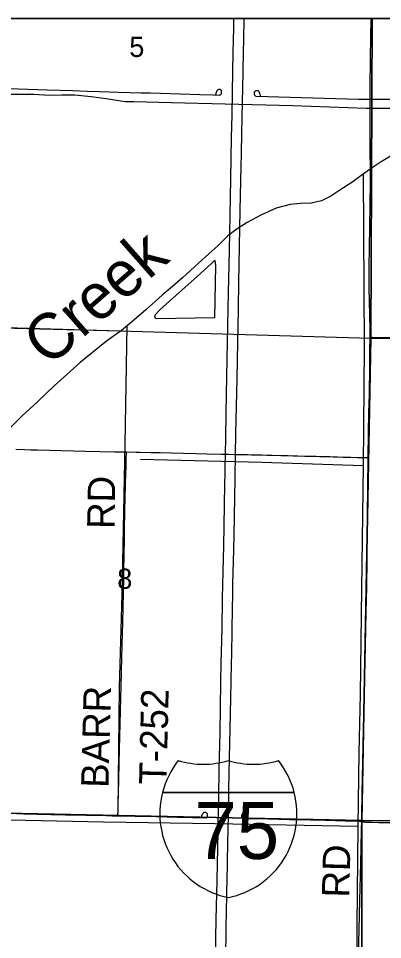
# Model space of a CAD drawing. Extents: x -59 to 43, y 0 to 22.
# Drawn here: x 26.579 to 27.334, y 18.99 to 20.9 of the extents above; entities that cross this region are included whole.
import ezdxf

# ---------------------------------------------------------------- set-up
doc = ezdxf.new("R2010")
doc.units = 0
for name, color, linetype in [('Default', 7, 'Continuous'), ('GM_X_Interchange_Ramps', 7, 'Continuous'), ('GM_X_Interstate_Location', 7, 'Continuous'), ('GM_X_Interstate_Route', 7, 'Continuous'), ('GM_X_Interstate_Shield', 7, 'Continuous'), ('GM_X_Major_River', 7, 'Continuous'), ('GM_X_Major_River_Text', 7, 'Continuous'), ('GM_X_Minor_Lake', 7, 'Continuous'), ('GM_X_Minor_River', 7, 'Continuous'), ('GM_X_Section', 7, 'Continuous'), ('GM_X_Section_Text', 7, 'Continuous'), ('GM_X_Township_Road', 7, 'Continuous'), ('GM_X_Township_Road_Text', 7, 'Continuous'), ('SH_Data', 7, 'Continuous')]:
    doc.layers.add(name, color=color, linetype=linetype)

msp = doc.modelspace()

# ---------------------------------------------------------------- linework, layer by layer
at = {"layer": 'Default'}
for points in [[(27.313, 20.9), (26.3353, 20.9), (26.3156, 20.2658), (27.3102, 20.2373)], [(28.32, 20.9), (27.313, 20.9), (27.3102, 20.2373), (28.3185, 20.2315)]]:
    msp.add_lwpolyline(points, close=True, dxfattribs=at)
at = {"layer": 'GM_X_Interchange_Ramps'}
msp.add_lwpolyline([(29.3371, 20.9), (25.208, 20.9)], dxfattribs=at)
at = {"layer": 'GM_X_Interstate_Route'}
for points in [[(26.9938, 19.2484), (26.9946, 19.2857), (26.9958, 19.3435), (26.9973, 19.4187), (26.9983, 19.4703), (26.9993, 19.5256), (27, 19.5623), (27.0015, 19.6344), (27.0026, 19.6978), (27.0038, 19.7531), (27.0049, 19.806), (27.0074, 19.9334), (27.0079, 19.957), (27.008, 19.9707), (27.0085, 19.9966), (27.0091, 20.031), (27.01, 20.0814), (27.0115, 20.1584), (27.0135, 20.2635), (27.0151, 20.3325), (27.0161, 20.3884), (27.0174, 20.4543), (27.0183, 20.4916), (27.0196, 20.5674), (27.0212, 20.6526), (27.0222, 20.6999), (27.0232, 20.7477), (27.0248, 20.8298), (27.0258, 20.8801), (27.0261, 20.9)], [(27.0148, 19.2478), (27.0159, 19.3027), (27.0172, 19.3673), (27.0184, 19.4264), (27.019, 19.4606), (27.0196, 19.4898), (27.0212, 19.5619), (27.0216, 19.5824), (27.0225, 19.6309), (27.0231, 19.6781), (27.0236, 19.7043), (27.024, 19.7279), (27.0251, 19.7739), (27.0256, 19.7981), (27.0263, 19.8292), (27.0285, 19.946), (27.0289, 19.9635), (27.0293, 19.9827), (27.0296, 19.9961), (27.0304, 20.0393), (27.0326, 20.153), (27.034, 20.2289), (27.0346, 20.2599), (27.0354, 20.3003), (27.0366, 20.3525), (27.0392, 20.5024), (27.0413, 20.5931), (27.0418, 20.6192), (27.0425, 20.6627), (27.0452, 20.7883), (27.0462, 20.8337), (27.0466, 20.8529), (27.0468, 20.8641), (27.0473, 20.8927), (27.0474, 20.9)], [(26.9881, 18.955), (26.9894, 19.0321), (26.9912, 19.1129), (26.9932, 19.2142), (26.9937, 19.2423), (26.9938, 19.2484)], [(26.9952, 18.2594), (27.0012, 18.5568), (27.0016, 18.5786), (27.0021, 18.6009), (27.0024, 18.6171), (27.0032, 18.6507), (27.0049, 18.7395), (27.0054, 18.765), (27.0059, 18.7886), (27.0065, 18.821), (27.0078, 18.8918), (27.0082, 18.9117), (27.0084, 18.9279), (27.0091, 18.9639), (27.0098, 19), (27.0102, 19.0162), (27.0116, 19.0814), (27.0123, 19.1224), (27.0125, 19.1374), (27.0128, 19.1579), (27.0134, 19.184), (27.0144, 19.2256), (27.0147, 19.2419), (27.0148, 19.2478)]]:
    msp.add_lwpolyline(points, dxfattribs=at)
at = {"layer": 'GM_X_Interstate_Shield'}
for p, q in [((26.878, 19.295), (27.1512, 19.295)), ((27.1512, 19.295), (26.878, 19.295)), ((27.1512, 19.295), (26.878, 19.295))]:
    msp.add_line(p, q, dxfattribs=at)
for centre, start, end in [((27.0501, 19.2514), 141.669, 165.8066), ((26.9627, 19.5314), 253.0091, 286.9909), ((27.0665, 19.5314), 253.0091, 286.9909), ((26.9791, 19.2514), 14.1934, 38.331), ((27.0501, 19.2514), 165.8066, 258.463), ((26.9791, 19.2514), 281.537, 14.1934)]:
    msp.add_arc(centre, 0.1776, start, end, dxfattribs=at)
at = {"layer": 'GM_X_Major_River'}
for points in [[(27.3646, 20.6227), (27.3316, 20.6029), (27.3105, 20.5889), (27.292, 20.5759), (27.2704, 20.5595), (27.2459, 20.5441), (27.2274, 20.5315), (27.2078, 20.5216), (27.1866, 20.5171), (27.1638, 20.5164), (27.1425, 20.5145), (27.1135, 20.5066), (27.0821, 20.4921), (27.0538, 20.4771), (27.0325, 20.464), (27.0134, 20.4493), (26.9929, 20.4288), (26.9744, 20.4117), (26.9524, 20.3927)], [(26.9524, 20.3927), (26.9192, 20.3622), (26.8985, 20.3445), (26.8771, 20.3265), (26.8432, 20.2956), (26.8135, 20.2703), (26.7927, 20.2532), (26.7619, 20.231), (26.7073, 20.1865), (26.6795, 20.1619), (26.6537, 20.1381), (26.6193, 20.1057), (26.5869, 20.0758), (26.5612, 20.0505), (26.543, 20.0319)]]:
    msp.add_lwpolyline(points, dxfattribs=at)
at = {"layer": 'GM_X_Minor_Lake'}
msp.add_line((26.9568, 20.3715), (26.8731, 20.2963), dxfattribs=at)
msp.add_lwpolyline([(26.8731, 20.2963), (26.8629, 20.2852), (26.8616, 20.2807), (26.8646, 20.2776), (26.9868, 20.2798), (26.9888, 20.3873), (26.9882, 20.3934), (26.9872, 20.398), (26.9833, 20.3954), (26.9802, 20.3925), (26.9568, 20.3715)], dxfattribs=at)
at = {"layer": 'GM_X_Minor_River'}
for points in [[(27.6392, 20.7146), (27.523, 20.7149), (27.3955, 20.7133), (27.3006, 20.713), (27.1481, 20.7185), (27.0082, 20.7225), (26.8966, 20.7249), (26.8185, 20.7271), (26.8003, 20.7273), (26.7825, 20.7297), (26.7613, 20.7333), (26.73, 20.7373), (26.6963, 20.7409), (26.6685, 20.7406), (26.6446, 20.7401), (26.6105, 20.7426), (26.5764, 20.7424), (26.5491, 20.7425)], [(27.2943, 20.5775), (27.296, 20.2192), (27.2947, 20.0523), (27.2939, 19.9721), (27.2909, 19.7174), (27.288, 19.4981), (27.2854, 19.3781), (27.284, 19.2766), (27.2833, 19.2245), (27.2809, 19.0196), (27.2803, 18.8364), (27.2792, 18.7725)], [(26.8041, 20.2627), (26.8002, 20.017), (26.797, 19.8761), (26.7936, 19.7047), (26.7882, 19.5136), (26.7854, 19.2559)], [(26.7908, 20.2519), (26.6233, 20.2559), (26.5445, 20.2576)], [(27.2939, 19.9721), (27.0838, 19.9796), (26.8323, 19.9857)], [(27.2833, 19.2245), (26.9862, 19.23), (26.7559, 19.2339), (26.5288, 19.2385)]]:
    msp.add_lwpolyline(points, dxfattribs=at)
at = {"layer": 'GM_X_Section'}
for points in [[(26.3156, 20.2658), (27.3102, 20.2373), (27.2913, 19.2374), (26.283, 19.2582)], [(27.3102, 20.2373), (28.3185, 20.2315), (28.3099, 19.2353), (27.2913, 19.2374)], [(26.283, 19.2582), (27.2913, 19.2374), (27.2918, 18.2449), (26.2659, 18.2705), (26.2571, 18.8106)], [(27.2913, 19.2374), (28.3099, 19.2353), (28.3019, 18.2312), (27.8326, 18.2227), (27.2918, 18.2449)]]:
    msp.add_lwpolyline(points, close=True, dxfattribs=at)
at = {"layer": 'GM_X_Township_Road'}
msp.add_line((26.8031, 20.0012), (26.8231, 20.0009), dxfattribs=at)
for points in [[(27.3084, 20.7324), (27.3086, 20.7542), (27.3094, 20.8195), (27.3109, 20.9)], [(26.537, 20.7551), (26.6396, 20.7522), (26.6911, 20.7504), (26.7228, 20.7494), (26.7477, 20.7487), (26.7676, 20.748), (26.7862, 20.7474), (26.8335, 20.746), (26.8527, 20.7454), (26.8739, 20.7448), (26.9143, 20.7435), (26.9553, 20.7421), (26.9826, 20.7414), (26.9963, 20.7412), (26.9973, 20.7414), (26.998, 20.7416), (26.999, 20.7423), (26.9997, 20.7432), (27.0002, 20.7445), (27.0004, 20.7453), (27.0005, 20.746), (27.0006, 20.7466), (27.0006, 20.7473), (27.0006, 20.7482), (27.0005, 20.749), (27.0002, 20.75), (26.9995, 20.7511), (26.9989, 20.7516), (26.9978, 20.7523), (26.9971, 20.7525), (26.9964, 20.7526), (26.9957, 20.7526), (26.9948, 20.7525), (26.994, 20.7523), (26.9934, 20.7521), (26.9927, 20.7517), (26.9921, 20.7513), (26.9915, 20.7508), (26.9909, 20.7501), (26.9905, 20.7495), (26.9901, 20.7487), (26.9898, 20.7479), (26.9893, 20.7466), (26.989, 20.7456), (26.9888, 20.7447), (26.9885, 20.7436), (26.9881, 20.7416)], [(27.0814, 20.7387), (27.081, 20.7406), (27.0805, 20.7426), (27.0801, 20.7439), (27.0797, 20.7453), (27.0793, 20.7466), (27.0788, 20.7474), (27.0782, 20.7482), (27.0773, 20.7492), (27.0767, 20.7495), (27.0761, 20.7498), (27.0752, 20.75), (27.0741, 20.7501), (27.0729, 20.7501), (27.0718, 20.7499), (27.071, 20.7495), (27.0702, 20.749), (27.0695, 20.7484), (27.0689, 20.7477), (27.0684, 20.747), (27.0681, 20.746), (27.0679, 20.7449), (27.068, 20.7438), (27.0682, 20.7427), (27.0685, 20.7419), (27.0691, 20.7408), (27.0698, 20.7399), (27.0708, 20.7392), (27.0716, 20.7388), (27.0725, 20.7386), (27.213, 20.7347), (27.2845, 20.7324), (27.2969, 20.7323), (27.3084, 20.7324)], [(27.3084, 20.2395), (27.3084, 20.2557), (27.3069, 20.3415), (27.3068, 20.3912), (27.307, 20.4192), (27.308, 20.4751), (27.3085, 20.5074), (27.3091, 20.5684), (27.309, 20.597), (27.3088, 20.6187), (27.3085, 20.6722), (27.3084, 20.7275), (27.3084, 20.7324)], [(27.3084, 20.7324), (27.3249, 20.7326), (27.443, 20.7325), (27.5052, 20.7325), (27.5736, 20.7323), (27.6265, 20.7321), (27.6482, 20.7318), (27.6607, 20.7316), (27.6855, 20.7315), (27.7042, 20.7318), (27.7259, 20.7319), (27.813, 20.7319), (27.8814, 20.7323), (27.9031, 20.7324), (27.9156, 20.7327), (27.9529, 20.733), (27.9809, 20.7329), (28.0182, 20.733), (28.0866, 20.7333), (28.2234, 20.7343), (28.2576, 20.7345), (28.3104, 20.7348), (28.3177, 20.7348)], [(27.3047, 19.9895), (27.3055, 20.04), (27.3062, 20.0822), (27.307, 20.1208), (27.3071, 20.1382), (27.3077, 20.1618), (27.308, 20.1898), (27.3082, 20.214), (27.3084, 20.2358), (27.3084, 20.2395)], [(27.3084, 20.2395), (27.3136, 20.2395), (27.3913, 20.2388), (27.4534, 20.2384), (27.4938, 20.2378), (27.5341, 20.2373), (27.5493, 20.2373)], [(26.5737, 20.0067), (26.5917, 20.0062), (26.6048, 20.0059), (26.6191, 20.0055), (26.7185, 20.0031), (26.7788, 20.0017), (26.7975, 20.0013), (26.8031, 20.0012)], [(26.7857, 19.2468), (26.7859, 19.2584), (26.7862, 19.2715), (26.7867, 19.2926), (26.7874, 19.3237), (26.789, 19.3858), (26.7897, 19.4113), (26.7904, 19.4374), (26.7917, 19.4908), (26.7924, 19.5157), (26.7933, 19.5461), (26.7946, 19.602), (26.7957, 19.6474), (26.7971, 19.7102), (26.7977, 19.7387), (26.798, 19.7543), (26.7985, 19.7909), (26.7989, 19.8189), (26.7992, 19.8432), (26.8, 19.8748), (26.8002, 19.8823), (26.8007, 19.9022), (26.8015, 19.9364), (26.8025, 19.973), (26.8029, 19.9873), (26.8031, 20.0002), (26.8031, 20.0012)], [(26.8231, 20.0009), (26.831, 20.0008), (26.8541, 20.0003), (26.8733, 20), (26.8969, 19.9994), (26.9218, 19.9988), (26.9479, 19.9981), (26.9702, 19.9974), (27.0001, 19.9967), (27.0085, 19.9966), (27.015, 19.9964), (27.0296, 19.9961), (27.0461, 19.9958), (27.0541, 19.9956), (27.0628, 19.9954), (27.0771, 19.9951), (27.084, 19.9949), (27.0952, 19.9947), (27.1057, 19.9944), (27.1231, 19.994), (27.1386, 19.9937), (27.1498, 19.9934), (27.1585, 19.9932), (27.1734, 19.9928), (27.1815, 19.9926), (27.1964, 19.9922), (27.2034, 19.9921)], [(27.2034, 19.9921), (27.2064, 19.992), (27.2144, 19.9918), (27.225, 19.9915), (27.2318, 19.9913), (27.2328, 19.9913)], [(27.2328, 19.9913), (27.2412, 19.9911), (27.2524, 19.9907), (27.2685, 19.9902), (27.2827, 19.9899), (27.2937, 19.9897), (27.3003, 19.9896), (27.3047, 19.9895)], [(27.2911, 19.2348), (27.2911, 19.245), (27.292, 19.2947), (27.2934, 19.3581), (27.2951, 19.4277), (27.2969, 19.5054), (27.2978, 19.5414), (27.2984, 19.5663), (27.2991, 19.5993), (27.3006, 19.6701), (27.3009, 19.6956), (27.3015, 19.7211), (27.3026, 19.7777), (27.3032, 19.8517), (27.3031, 19.8715), (27.3039, 19.9268), (27.3047, 19.9895)], [(26.2823, 19.2577), (26.299, 19.2577), (26.3207, 19.2576), (26.3362, 19.2572), (26.4137, 19.2552), (26.4819, 19.2536), (26.5222, 19.2529), (26.5595, 19.2522), (26.5904, 19.2511), (26.6462, 19.2498), (26.6772, 19.249), (26.7194, 19.2479)], [(26.9716, 19.2479), (26.9716, 19.2486), (26.9714, 19.2496), (26.9712, 19.2504), (26.9707, 19.2514), (26.9703, 19.252), (26.9697, 19.2526), (26.9689, 19.2532), (26.968, 19.2536), (26.9669, 19.2538), (26.9659, 19.2537), (26.9649, 19.2536), (26.964, 19.2534), (26.9631, 19.253), (26.9625, 19.2526), (26.9619, 19.2519), (26.9613, 19.251), (26.9605, 19.2495), (26.9599, 19.2482)], [(27.0555, 19.2416), (27.0546, 19.2442), (27.0544, 19.245), (27.0539, 19.2464), (27.0534, 19.2476), (27.053, 19.2485), (27.0525, 19.2494), (27.052, 19.2502), (27.0516, 19.2507), (27.051, 19.2512), (27.0505, 19.2515), (27.0499, 19.2518), (27.049, 19.2521), (27.0481, 19.2522), (27.0473, 19.2522), (27.0467, 19.2522), (27.0457, 19.252), (27.045, 19.2517), (27.0441, 19.2512), (27.0436, 19.2507), (27.043, 19.2501), (27.0426, 19.2493), (27.0423, 19.2486), (27.0421, 19.2479), (27.0419, 19.247), (27.0419, 19.2462), (27.0421, 19.2453), (27.0423, 19.2443), (27.0427, 19.2434), (27.0431, 19.2428), (27.0437, 19.2423), (27.0443, 19.2419), (27.045, 19.2417), (27.0459, 19.2415), (27.0467, 19.2414), (27.063, 19.2411), (27.0974, 19.2404), (27.1411, 19.2393), (27.1849, 19.2386), (27.2161, 19.2377), (27.2568, 19.2367), (27.2857, 19.2357), (27.2873, 19.2355), (27.289, 19.2353), (27.2911, 19.2348)], [(26.7194, 19.2479), (26.7612, 19.2472), (26.7736, 19.247), (26.7857, 19.2468)], [(26.7857, 19.2468), (26.8211, 19.246), (26.865, 19.2453), (26.9089, 19.2442), (26.9402, 19.2435), (26.9581, 19.2431), (26.9623, 19.2431), (26.9679, 19.2429), (26.9688, 19.243)], [(26.9599, 19.2482), (26.9592, 19.2463), (26.958, 19.2435)], [(26.9688, 19.243), (26.9696, 19.2432), (26.9702, 19.2437), (26.9707, 19.2443), (26.9711, 19.2449), (26.9714, 19.2458), (26.9716, 19.247), (26.9716, 19.2479)], [(27.2788, 18.737), (27.2789, 18.7447), (27.28, 18.7857), (27.2815, 18.8267), (27.2822, 18.8553), (27.2834, 18.9094), (27.2847, 18.9641), (27.2859, 19.01), (27.2875, 19.0722), (27.2884, 19.1219), (27.2897, 19.1791), (27.2908, 19.2201), (27.2911, 19.2348)], [(27.2911, 19.2348), (27.2941, 19.2343), (27.296, 19.2341), (27.2974, 19.2339), (27.2991, 19.2338), (27.3079, 19.2337), (27.3118, 19.2336)], [(27.3118, 19.2336), (27.3266, 19.2333), (27.3608, 19.2333), (27.4168, 19.2328), (27.4665, 19.232), (27.4945, 19.2317), (27.5412, 19.231), (27.5972, 19.23), (27.6438, 19.2294), (27.6811, 19.2288), (27.7931, 19.2271), (27.818, 19.2269), (27.8522, 19.227), (27.9237, 19.2274), (28.0108, 19.2281), (28.073, 19.2288), (28.1228, 19.2289), (28.2347, 19.2303), (28.2814, 19.2313), (28.3031, 19.2315), (28.3043, 19.2315)]]:
    msp.add_lwpolyline(points, dxfattribs=at)
at = {"layer": 'SH_Data'}
msp.add_lwpolyline([(23.5167, 20.9), (30.3167, 20.9), (30.3167, 14.1), (23.5167, 14.1)], close=True, dxfattribs=at)

# ---------------------------------------------------------------- texts
at = {"layer": 'GM_X_Interstate_Location'}
for s in ['-', '.', ',']:
    msp.add_text(s, height=0.000189, dxfattribs=at).set_placement((27.0146, 19.2194))
msp.add_text('75', height=0.000189, rotation=0, dxfattribs=at).set_placement((26.9759, 19.1802))
at = {"layer": 'GM_X_Interstate_Shield'}
msp.add_text('75', height=0.11837, dxfattribs=at).set_placement((26.9439, 19.1574))
at = {"layer": 'GM_X_Major_River_Text'}
msp.add_text('Creek', height=0.09476, rotation=41.3161, dxfattribs=at).set_placement((26.6424, 20.1752))
at = {"layer": 'GM_X_Section_Text'}
for s, p in [('5', (26.8092, 20.8201)), ('8', (26.7842, 19.7175))]:
    msp.add_text(s, height=0.0419, rotation=0, dxfattribs=at).set_placement(p)
at = {"layer": 'GM_X_Township_Road_Text'}
for s, rotation, p in [('RD', 89.0151, (26.7784, 19.8413)), ('BARR', 88.4976, (26.7659, 19.3044)), ('T-252', 88.6108, (26.8861, 19.3112)), ('RD', 88.53, (27.2652, 19.0769))]:
    msp.add_text(s, height=0.05682, rotation=rotation, dxfattribs=at).set_placement(p)

doc.saveas('drawing.dxf')
